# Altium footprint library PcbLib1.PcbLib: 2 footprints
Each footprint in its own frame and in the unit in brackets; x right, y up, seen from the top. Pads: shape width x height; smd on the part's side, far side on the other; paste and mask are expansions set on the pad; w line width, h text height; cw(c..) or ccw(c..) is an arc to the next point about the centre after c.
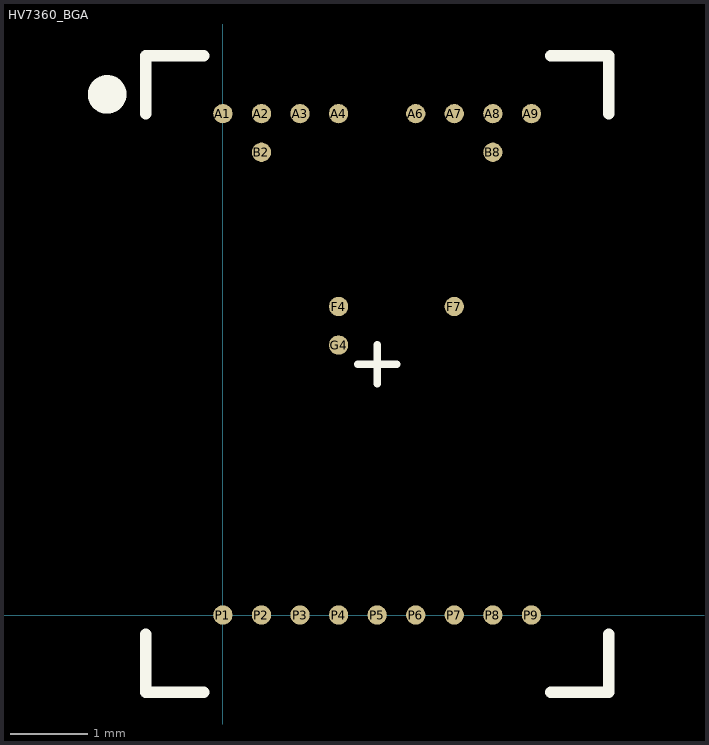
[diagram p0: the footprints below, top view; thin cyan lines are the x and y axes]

## HV7360_BGA [mm]
pads (22):
  round 0.25 smd: A1(0,6.5) A2(0.5,6.5) A3(1,6.5) A4(1.5,6.5) A6(2.5,6.5) A7(3,6.5) A8(3.5,6.5) A9(4,6.5) B2(0.5,6) B8(3.5,6) F4(1.5,4) F7(3,4) G4(1.5,3.5) P1(0,0) P2(0.5,0) P3(1,0) P4(1.5,0) P5(2,0) P6(2.5,0) P7(3,0) P8(3.5,0) P9(4,0)
Top Overlay:
  circle w0.3: c-1.5,6.75 r0.1
  lines w0.1: 1.75,3.25 2.25,3.25 ; 2,3 2,3.5
  lines w0.15: -1,-0.25 -1,-1 -0.25,-1 ; -1,6.5 -1,7.25 -0.25,7.25 ; 4.25,-1 5,-1 5,-0.25 ; 4.25,7.25 5,7.25 5,6.5

## PCBComponent_1 [mm]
